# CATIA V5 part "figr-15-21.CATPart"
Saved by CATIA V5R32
Part number: Part1
Bounding box of the stored display mesh (mm): x -81.56 to 85.56, y -36.965 to 25.965, z 0 to 42
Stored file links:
  D:\PROJECTS\Project 2022\CATIA V5 6R 2022\Resources\Part Files\c15_catia_v5_6r2022_prt\figr-15-21.CATPart
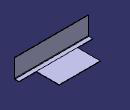
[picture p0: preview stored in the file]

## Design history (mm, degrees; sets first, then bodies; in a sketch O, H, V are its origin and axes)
SheetMetalParameters1: Thickness 1, BendRadius 1, KFactor 0.325257 {= log(min(100,max(20*SheetMetalParameters1.BendRadius,SheetMetalParameters1.Thickness)/SheetMetalParameters1.Thickness))/log(100)/2}, ReliefRadialLength 1, ReliefAxialLength 2, MinimumBendRadius 0
Body1 (main body)
  Sketch1 on xy-plane, origin (0, 0, 0), H (1, 0, 0), V (0, 1, 0)
    line L1 (-46.5596, 25.9646) -> (46.5596, 25.9646)
    line L2 (46.5596, 25.9646) -> (46.5596, -25.9646)
    line L3 (46.5596, -25.9646) -> (-46.5596, -25.9646)
    line L4 (-46.5596, -25.9646) -> (-46.5596, 25.9646)
    horizontal: L1 H, L3 H
    vertical: L2 V, L4 V
    symmetry: L1 L3 H, L4 L2 V
  Wall1: Thickness 1, Profile Sketch1
  d_NewWallOnEdge1: NewWallOnEdge_Edge edge [face of Wall1 | face of Wall1], NewWallOnEdge_Length 42, NewWallOnEdge_HeightLimitOffset 0, NewWallOnEdge_WidthOffset1 39, NewWallOnEdge_WidthOffset2 35, NewWallOnEdge_Angle 90, NewWallOnEdge_BendRadiusValue 1 {= SheetMetalParameters1.BendRadius}, NewWallOnEdge_BendTable SheetMetalParameters1, KFacteur 0.325257 {= log(min(100,max(20*d_NewWallOnEdge1.Radius,SheetMetalParameters1.Thickness)/SheetMetalParameters1.Thickness))/log(100)/2}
